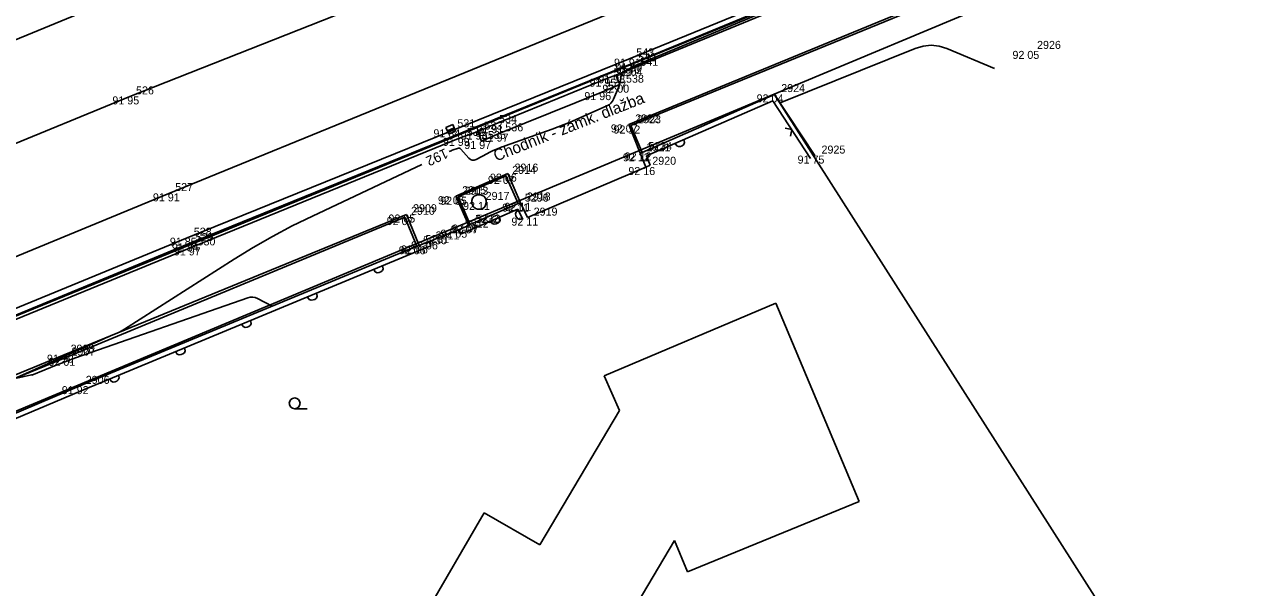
# Model space of a CAD drawing. Extents: x -711081 to -709338, y -1025122 to -1024092.
# Drawn here: x -710097.86 to -710055.27, y -1024672.2 to -1024652.5 of the extents above; entities that cross this region are included whole.
import ezdxf

# ---------------------------------------------------------------- set-up
doc = ezdxf.new("R2010")
doc.units = 0
for name, color, linetype in [('Ex_Contour Labels', 7, 'Continuous'), ('Ex_Major Contours', 7, 'Continuous'), ('Z_body', 7, 'Continuous'), ('Z_body_cisla', 7, 'Continuous'), ('Z_body_vysky_redukovane', 7, 'Continuous'), ('Z_chodnik', 7, 'Continuous'), ('Z_katastr_hranice', 7, 'Continuous'), ('Z_komunikace', 7, 'Continuous'), ('Z_komunikace_osa', 7, 'Continuous'), ('Z_obruba', 7, 'Continuous'), ('Z_ploty', 7, 'Continuous'), ('Z_ploty_znacky', 7, 'Continuous'), ('Z_popisy', 7, 'Continuous'), ('Z_rozhranni', 7, 'Continuous'), ('Z_site_kanalizace_znaky', 7, 'Continuous'), ('Z_vdz12_plna', 7, 'Continuous'), ('Z_vdz25_plna', 7, 'Continuous'), ('Z_vstupy', 7, 'Continuous'), ('Z_znaky_kultur', 7, 'Continuous')]:
    doc.layers.add(name, color=color, linetype=linetype)

# ---------------------------------------------------------------- blocks, each defined once
blk = doc.blocks.new('POINT_DISPLAY')
blk.add_line((0, 0), (0, 0))
blk = doc.blocks.new('Z216')
for p, q in [((-0.17, 0), (-0.15, 0.1)), ((-0.15, 0.1), (-0.1, 0.15)), ((-0.1, 0.15), (-0.03, 0.17)), ((-0.03, 0.17), (0.03, 0.17)), ((0.03, 0.17), (0.1, 0.15)), ((0.1, 0.15), (0.15, 0.1)), ((0.15, 0.1), (0.17, 0))]:
    blk.add_line(p, q)
blk = doc.blocks.new('Z212')
for p, q in [((-0.17, 0.17), (0, 0)), ((0, 0), (0.17, 0.17))]:
    blk.add_line(p, q)
blk = doc.blocks.new('Z620')
for p, q in [((-0.25, 0.05), (-0.23, 0.13)), ((-0.25, -0.05), (-0.25, 0.05)), ((-0.23, 0.13), (-0.17, 0.2)), ((-0.17, 0.2), (-0.05, 0.25)), ((-0.05, 0.25), (0.05, 0.25)), ((0.05, 0.25), (0.17, 0.2)), ((0.17, 0.2), (0.23, 0.13)), ((0.23, 0.13), (0.25, 0.05)), ((0.25, 0.05), (0.25, -0.05)), ((-0.2, -0.17), (-0.25, -0.05)), ((-0.13, -0.23), (-0.2, -0.17)), ((-0.05, -0.25), (-0.13, -0.23)), ((0.05, -0.25), (-0.05, -0.25)), ((0.13, -0.23), (0.05, -0.25)), ((0.2, -0.17), (0.13, -0.23)), ((0.25, -0.05), (0.2, -0.17))]:
    blk.add_line(p, q)
blk = doc.blocks.new('Z46260')
for p, q in [((0.13, 0.13), (-0.13, 0.13)), ((-0.13, 0.13), (-0.13, -0.13)), ((0.13, 0), (-0.13, 0)), ((0.13, -0.13), (0.13, 0.13)), ((-0.13, -0.13), (0.13, -0.13))]:
    blk.add_line(p, q)
blk = doc.blocks.new('Z304')
blk.add_line((0, -0.19), (0.44, -0.19))
blk.add_circle((0, 0), 0.188)

msp = doc.modelspace()

# ---------------------------------------------------------------- linework, layer by layer
at = {"layer": 'Ex_Major Contours'}
for points in [[(-710082.998, -1024656.952), (-710082.993, -1024656.949), (-710082.958, -1024656.933), (-710082.923, -1024656.918), (-710082.887, -1024656.904), (-710082.851, -1024656.89), (-710082.707, -1024656.837), (-710082.672, -1024656.829), (-710082.64, -1024656.831), (-710082.611, -1024656.844), (-710082.584, -1024656.868), (-710082.307, -1024657.18), (-710082.25, -1024657.229), (-710082.188, -1024657.253), (-710082.122, -1024657.252), (-710082.052, -1024657.226), (-710081.651, -1024657.012), (-710081.602, -1024656.987), (-710081.552, -1024656.962), (-710081.502, -1024656.939), (-710081.452, -1024656.917), (-710081.248, -1024656.83), (-710081.197, -1024656.809), (-710081.146, -1024656.788), (-710081.094, -1024656.768), (-710081.043, -1024656.749), (-710079.398, -1024656.162), (-710079.186, -1024656.084), (-710078.975, -1024656.002), (-710078.766, -1024655.917), (-710078.558, -1024655.828), (-710077.481, -1024655.354), (-710077.404, -1024655.312), (-710077.338, -1024655.257), (-710077.285, -1024655.191), (-710077.243, -1024655.113), (-710077.071, -1024654.707), (-710077.052, -1024654.658), (-710077.036, -1024654.608), (-710077.023, -1024654.557), (-710077.013, -1024654.506), (-710076.978, -1024654.298), (-710076.964, -1024654.249), (-710076.941, -1024654.207), (-710076.909, -1024654.172), (-710076.867, -1024654.143), (-710076.658, -1024654.031), (-710076.607, -1024654.005), (-710076.556, -1024653.98), (-710076.504, -1024653.956), (-710076.452, -1024653.933), (-710070.488, -1024651.437)], [(-710071.416, -1024655.245), (-710066.695, -1024653.346), (-710066.416, -1024653.262), (-710066.138, -1024653.235), (-710065.86, -1024653.264), (-710065.582, -1024653.351), (-710063.917, -1024654.04)], [(-710098.126, -1024664.844), (-710096.814, -1024664.267), (-710096.63, -1024664.186), (-710096.445, -1024664.105), (-710096.261, -1024664.023), (-710096.077, -1024663.941), (-710095.097, -1024663.505), (-710095.034, -1024663.477), (-710094.971, -1024663.449), (-710094.908, -1024663.422), (-710094.845, -1024663.395), (-710094.592, -1024663.287), (-710094.529, -1024663.259), (-710094.468, -1024663.228), (-710094.408, -1024663.195), (-710094.349, -1024663.159), (-710090.513, -1024660.71), (-710089.849, -1024660.3), (-710089.172, -1024659.913), (-710088.483, -1024659.547), (-710087.782, -1024659.203), (-710083.948, -1024657.399)], [(-710089.191, -1024662.356), (-710089.697, -1024662.087), (-710089.782, -1024662.052), (-710089.868, -1024662.036), (-710089.956, -1024662.039), (-710090.045, -1024662.061), (-710096.064, -1024664.161), (-710096.219, -1024664.217), (-710096.374, -1024664.274), (-710096.528, -1024664.334), (-710096.681, -1024664.396), (-710097.591, -1024664.772), (-710097.594, -1024664.772), (-710097.596, -1024664.772), (-710097.598, -1024664.771), (-710097.6, -1024664.769), (-710097.605, -1024664.758), (-710097.606, -1024664.755), (-710097.608, -1024664.754), (-710097.61, -1024664.753), (-710097.613, -1024664.753), (-710098.116, -1024664.874)]]:
    msp.add_lwpolyline(points, dxfattribs=at)
at = {"layer": 'Z_chodnik'}
for p, q in [((-710076.71, -1024656), (-710063.76, -1024650.68)), ((-710076.71, -1024656), (-710076.31, -1024657.01)), ((-710082.76, -1024658.51), (-710080.94, -1024657.72)), ((-710080.94, -1024657.72), (-710080.5, -1024658.74)), ((-710082.76, -1024658.51), (-710082.31, -1024659.53)), ((-710096.46, -1024664.05), (-710084.49, -1024659.15)), ((-710084.49, -1024659.15), (-710084.05, -1024660.23)), ((-710109.48, -1024669.39), (-710096.46, -1024664.05))]:
    msp.add_line(p, q, dxfattribs=at)
at = {"layer": 'Z_katastr_hranice'}
for p, q in [((-710014.43, -1024631.03), (-710071.63, -1024654.94)), ((-710073.67, -1024652.69), (-710032.84, -1024636.02)), ((-710119.96, -1024671.62), (-710073.67, -1024652.69)), ((-710071.63, -1024654.94), (-710101.21, -1024667.3)), ((-710071.63, -1024654.94), (-710053.32, -1024683.61)), ((-710077.57, -1024664.79), (-710071.57, -1024662.25)), ((-710071.57, -1024662.25), (-710068.65, -1024669.18)), ((-710077.04, -1024666), (-710077.57, -1024664.79)), ((-710079.82, -1024670.7), (-710077.04, -1024666)), ((-710068.65, -1024669.18), (-710074.66, -1024671.64)), ((-710083.88, -1024673.19), (-710081.77, -1024669.58)), ((-710081.77, -1024669.58), (-710079.82, -1024670.7)), ((-710075.11, -1024670.55), (-710076.42, -1024672.75)), ((-710074.66, -1024671.64), (-710075.11, -1024670.55))]:
    msp.add_line(p, q, dxfattribs=at)
at = {"layer": 'Z_komunikace'}
for p, q in [((-710076.6, -1024653.87), (-710063.49, -1024648.47)), ((-710107.96, -1024657.04), (-710095.33, -1024651.88)), ((-710092.09, -1024660.16), (-710076.6, -1024653.87)), ((-710104.53, -1024665.29), (-710092.09, -1024660.16))]:
    msp.add_line(p, q, dxfattribs=at)
at = {"layer": 'Z_komunikace_osa'}
for p, q in [((-710094.17, -1024655.02), (-710078.34, -1024648.78)), ((-710106.6, -1024660.12), (-710094.17, -1024655.02))]:
    msp.add_line(p, q, dxfattribs=at)
at = {"layer": 'Z_obruba'}
for p, q in [((-710076.54, -1024654.02), (-710063.35, -1024648.61)), ((-710076.64, -1024656.04), (-710063.7, -1024650.74)), ((-710077.17, -1024654.28), (-710076.54, -1024654.02)), ((-710081.48, -1024656.03), (-710077.48, -1024654.4)), ((-710077.48, -1024654.4), (-710077.17, -1024654.28)), ((-710081.99, -1024656.25), (-710081.48, -1024656.03)), ((-710076.64, -1024656.04), (-710076.25, -1024656.98)), ((-710092.02, -1024660.3), (-710082.61, -1024656.47)), ((-710082.61, -1024656.47), (-710081.99, -1024656.25)), ((-710082.68, -1024658.53), (-710081.01, -1024657.8)), ((-710081.01, -1024657.8), (-710080.58, -1024658.77)), ((-710082.68, -1024658.53), (-710082.26, -1024659.5)), ((-710096.43, -1024664.16), (-710084.55, -1024659.24)), ((-710084.55, -1024659.24), (-710084.13, -1024660.26)), ((-710104.47, -1024665.4), (-710092.02, -1024660.3)), ((-710109.42, -1024669.44), (-710096.43, -1024664.16))]:
    msp.add_line(p, q, dxfattribs=at)
at = {"layer": 'Z_ploty'}
for p, q in [((-710076.25, -1024656.98), (-710071.61, -1024654.95)), ((-710071.61, -1024654.95), (-710070.2, -1024657.09)), ((-710076.09, -1024657.1), (-710071.67, -1024655.17)), ((-710071.67, -1024655.17), (-710070.35, -1024657.19)), ((-710076.31, -1024657.01), (-710076.25, -1024656.98)), ((-710076.12, -1024657.49), (-710076.31, -1024657.01)), ((-710076.12, -1024657.49), (-710075.96, -1024657.43)), ((-710075.96, -1024657.43), (-710076.09, -1024657.1)), ((-710082.26, -1024659.5), (-710080.58, -1024658.77)), ((-710080.58, -1024658.77), (-710080.5, -1024658.74)), ((-710080.5, -1024658.74), (-710080.26, -1024659.26)), ((-710082.19, -1024659.66), (-710080.59, -1024658.96)), ((-710080.59, -1024658.96), (-710080.42, -1024659.33)), ((-710082.67, -1024659.68), (-710082.31, -1024659.53)), ((-710082.31, -1024659.53), (-710082.26, -1024659.5)), ((-710082.67, -1024659.68), (-710082.6, -1024659.84)), ((-710082.6, -1024659.84), (-710082.19, -1024659.66)), ((-710095.94, -1024665.15), (-710084.13, -1024660.26)), ((-710095.87, -1024665.31), (-710083.99, -1024660.39)), ((-710084.13, -1024660.26), (-710084.05, -1024660.23)), ((-710084.05, -1024660.23), (-710083.7, -1024660.09)), ((-710083.99, -1024660.39), (-710083.64, -1024660.25)), ((-710083.7, -1024660.09), (-710083.64, -1024660.25)), ((-710108.1, -1024670.3), (-710095.94, -1024665.15)), ((-710108.57, -1024670.69), (-710095.87, -1024665.31))]:
    msp.add_line(p, q, dxfattribs=at)
at = {"layer": 'Z_rozhranni'}
for p, q in [((-710077.17, -1024654.28), (-710077.03, -1024654.61)), ((-710081.25, -1024656.32), (-710077.66, -1024654.87)), ((-710077.66, -1024654.87), (-710077.03, -1024654.61)), ((-710081.99, -1024656.25), (-710081.86, -1024656.58)), ((-710081.86, -1024656.58), (-710081.25, -1024656.32))]:
    msp.add_line(p, q, dxfattribs=at)
at = {"layer": 'Z_vdz12_plna'}
for p, q in [((-710076.67, -1024653.7), (-710063.55, -1024648.32)), ((-710092.16, -1024659.96), (-710076.67, -1024653.7)), ((-710104.6, -1024665.07), (-710092.16, -1024659.96))]:
    msp.add_line(p, q, dxfattribs=at)
at = {"layer": 'Z_vdz25_plna'}
for p, q in [((-710092.8, -1024658.41), (-710077.15, -1024652.03)), ((-710105.27, -1024663.55), (-710092.8, -1024658.41))]:
    msp.add_line(p, q, dxfattribs=at)
at = {"layer": 'Z_vstupy'}
for p, q in [((-710076.12, -1024657.49), (-710080.26, -1024659.26)), ((-710083.7, -1024660.09), (-710082.67, -1024659.68))]:
    msp.add_line(p, q, dxfattribs=at)

# ---------------------------------------------------------------- block references
at = {"layer": 'Z_body'}
for p in [(-710062.66, -1024653.43), (-710076.67, -1024653.7), (-710076.6, -1024653.87), (-710076.54, -1024654.02), (-710077.48, -1024654.4), (-710077.17, -1024654.28), (-710077.66, -1024654.87), (-710077.03, -1024654.61), (-710071.61, -1024654.95), (-710094.17, -1024655.02), (-710082.94, -1024656.17), (-710081.48, -1024656.03), (-710076.71, -1024656), (-710076.64, -1024656.04), (-710082.61, -1024656.47), (-710081.99, -1024656.25), (-710081.86, -1024656.58), (-710081.25, -1024656.32), (-710076.31, -1024657.01), (-710076.25, -1024656.98), (-710070.2, -1024657.09), (-710076.12, -1024657.49), (-710081.01, -1024657.8), (-710080.94, -1024657.72), (-710092.8, -1024658.41), (-710082.76, -1024658.51), (-710082.68, -1024658.53), (-710081.95, -1024658.71), (-710080.58, -1024658.77), (-710080.5, -1024658.74), (-710084.49, -1024659.15), (-710084.55, -1024659.24), (-710082.31, -1024659.53), (-710082.26, -1024659.5), (-710080.26, -1024659.26), (-710092.16, -1024659.96), (-710082.67, -1024659.68), (-710092.09, -1024660.16), (-710092.02, -1024660.3), (-710084.13, -1024660.26), (-710084.05, -1024660.23), (-710083.7, -1024660.09), (-710096.46, -1024664.05), (-710096.43, -1024664.16), (-710095.94, -1024665.15)]:
    msp.add_blockref('POINT_DISPLAY', p, dxfattribs=at)
at = {"layer": 'Z_ploty_znacky'}
for name, p, rotation in [('Z212', (-710071.01, -1024656.18), 123.4), ('Z216', (-710074.94, -1024656.6), -156.40000000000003), ('Z216', (-710080.5, -1024659.15), 114.80000000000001), ('Z216', (-710081.39, -1024659.31), -156.5), ('Z216', (-710085.48, -1024661.01), -157.50000000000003), ('Z216', (-710087.79, -1024661.97), -157.50000000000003), ('Z216', (-710090.1, -1024662.92), -157.50000000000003), ('Z216', (-710092.41, -1024663.88), -157.50000000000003), ('Z216', (-710094.72, -1024664.83), -157.50000000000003)]:
    msp.add_blockref(name, p, dxfattribs=dict(at, rotation=rotation))
at = {"layer": 'Z_site_kanalizace_znaky', "rotation": 23.399999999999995}
msp.add_blockref('Z46260', (-710082.94, -1024656.17), dxfattribs=at)
at = {"layer": 'Z_site_kanalizace_znaky'}
msp.add_blockref('Z620', (-710081.95, -1024658.71), dxfattribs=at)
at = {"layer": 'Z_znaky_kultur'}
msp.add_blockref('Z304', (-710088.4, -1024665.75), dxfattribs=at)

# ---------------------------------------------------------------- texts
at = {"layer": 'Ex_Contour Labels'}
msp.add_text('192', height=0.35, rotation=205.202, dxfattribs=at).set_placement((-710083.138, -1024656.824))
at = {"layer": 'Z_body_cisla'}
for s, p in [('2926', (-710062.43, -1024653.36)), ('543', (-710076.45, -1024653.62)), ('542', (-710076.38, -1024653.79)), ('541', (-710076.31, -1024653.95)), ('539', (-710077.25, -1024654.32)), ('540', (-710076.95, -1024654.21)), ('537', (-710077.43, -1024654.79)), ('538', (-710076.81, -1024654.54)), ('526', (-710093.95, -1024654.95)), ('2924', (-710071.38, -1024654.87)), ('534', (-710081.25, -1024655.95)), ('2922', (-710076.49, -1024655.93)), ('2923', (-710076.42, -1024655.96)), ('531', (-710082.71, -1024656.1)), ('532', (-710082.38, -1024656.4)), ('533', (-710081.76, -1024656.18)), ('535', (-710081.64, -1024656.51)), ('536', (-710081.03, -1024656.24)), ('2921', (-710076.09, -1024656.94)), ('5234', (-710076.03, -1024656.9)), ('2925', (-710069.97, -1024657.02)), ('2914', (-710080.79, -1024657.73)), ('2916', (-710080.71, -1024657.65)), ('2920', (-710075.89, -1024657.41)), ('527', (-710092.58, -1024658.33)), ('2915', (-710082.54, -1024658.44)), ('2913', (-710082.46, -1024658.46)), ('2917', (-710081.72, -1024658.64)), ('2909', (-710084.26, -1024659.07)), ('5296', (-710080.35, -1024658.7)), ('2918', (-710080.28, -1024658.66)), ('2910', (-710084.33, -1024659.16)), ('5232', (-710082.09, -1024659.45)), ('5233', (-710082.04, -1024659.43)), ('2919', (-710080.04, -1024659.19)), ('528', (-710091.93, -1024659.89)), ('2912', (-710082.45, -1024659.61)), ('529', (-710091.87, -1024660.08)), ('530', (-710091.8, -1024660.23)), ('5230', (-710083.91, -1024660.19)), ('5231', (-710083.83, -1024660.15)), ('2911', (-710083.47, -1024660.02)), ('2908', (-710096.24, -1024663.98)), ('2907', (-710096.21, -1024664.08)), ('2906', (-710095.71, -1024665.07))]:
    msp.add_text(s, height=0.28, dxfattribs=at).set_placement(p)
at = {"layer": 'Z_body_vysky_redukovane'}
for s, p in [('92 05', (-710063.29, -1024653.71)), ('91 91', (-710077.23, -1024653.98)), ('91 90', (-710077.183, -1024654.15)), ('92 04', (-710077.17, -1024654.3)), ('91 95', (-710078.087, -1024654.68)), ('91 98', (-710077.777, -1024654.56)), ('91 96', (-710078.267, -1024655.15)), ('92 00', (-710077.637, -1024654.89)), ('92 04', (-710072.24, -1024655.23)), ('91 95', (-710094.777, -1024655.3)), ('91 84', (-710083.547, -1024656.45)), ('91 91', (-710082.04, -1024656.31)), ('92 07', (-710077.34, -1024656.28)), ('92 12', (-710077.247, -1024656.32)), ('91 99', (-710083.217, -1024656.75)), ('91 93', (-710082.597, -1024656.53)), ('91 97', (-710082.467, -1024656.86)), ('91 97', (-710081.857, -1024656.6)), ('92 12', (-710076.917, -1024657.29)), ('92 12', (-710076.857, -1024657.26)), ('91 75', (-710070.807, -1024657.37)), ('92 16', (-710076.727, -1024657.77)), ('92 07', (-710081.64, -1024658.08)), ('92 06', (-710081.57, -1024658)), ('91 91', (-710093.36, -1024658.69)), ('92 05', (-710083.39, -1024658.79)), ('92 05', (-710083.31, -1024658.81)), ('92 11', (-710082.51, -1024658.99)), ('92 11', (-710081.14, -1024659.05)), ('92 11', (-710081.06, -1024659.02)), ('92 05', (-710085.12, -1024659.43)), ('92 07', (-710085.18, -1024659.52)), ('92 07', (-710082.94, -1024659.81)), ('92 07', (-710082.89, -1024659.78)), ('92 11', (-710080.82, -1024659.54)), ('91 85', (-710092.767, -1024660.24)), ('92 05', (-710083.3, -1024659.96)), ('91 84', (-710092.697, -1024660.44)), ('91 97', (-710092.627, -1024660.58)), ('92 06', (-710084.76, -1024660.54)), ('92 06', (-710084.68, -1024660.51)), ('92 06', (-710084.33, -1024660.37)), ('91 99', (-710097.067, -1024664.33)), ('92 01', (-710097.013, -1024664.44)), ('91 92', (-710096.547, -1024665.43))]:
    msp.add_text(s, height=0.28, dxfattribs=at).set_placement(p)
at = {"layer": 'Z_popisy'}
msp.add_text('Chodník - zámk. dlažba', height=0.4, rotation=21.6, dxfattribs=at).set_placement((-710081.35, -1024657.3))

doc.saveas('drawing.dxf')
